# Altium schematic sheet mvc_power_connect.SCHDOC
size B
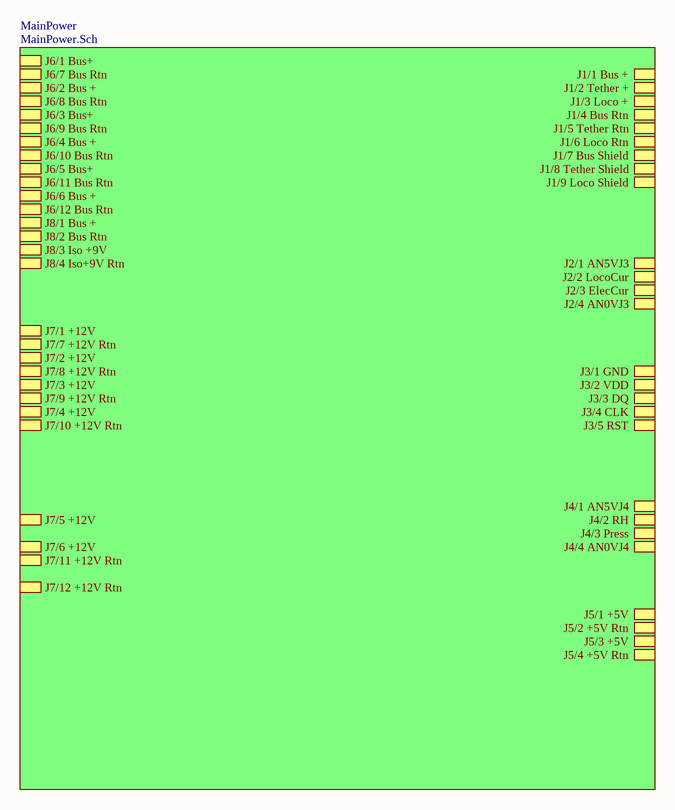
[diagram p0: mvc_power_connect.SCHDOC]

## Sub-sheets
MainPower = MainPower.Sch: J6/1 Bus+, J6/7 Bus Rtn, J6/2 Bus +, J6/8 Bus Rtn, J6/3 Bus+, J6/9 Bus Rtn, J6/4 Bus +, J6/10 Bus Rtn, J6/5 Bus+, J6/11 Bus Rtn, J6/6 Bus +, J6/12 Bus Rtn, J8/1 Bus +, J8/2 Bus Rtn, J8/3 Iso +9V, J8/4 Iso+9V Rtn, J5/1 +5V, J5/2 +5V Rtn, J5/3 +5V, J5/4 +5V Rtn, J7/1 +12V, J7/7 +12V Rtn, J7/2 +12V, J7/8 +12V Rtn, J7/3 +12V, J7/9 +12V Rtn, J7/4 +12V, J7/10 +12V Rtn, J7/5 +12V, J7/11 +12V Rtn, J7/6 +12V, J7/12 +12V Rtn, J4/1 AN5VJ4, J4/2 RH, J4/3 Press, J4/4 AN0VJ4, J2/1 AN5VJ3, J2/2 LocoCur, J2/3 ElecCur, J2/4 AN0VJ3, J3/1 GND, J3/2 VDD, J3/3 DQ, J3/4 CLK, J3/5 RST, J1/1 Bus +, J1/4 Bus Rtn, J1/7 Bus Shield, J1/2 Tether +, J1/5 Tether Rtn, J1/8 Tether Shield, J1/3 Loco +, J1/6 Loco Rtn, J1/9 Loco Shield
